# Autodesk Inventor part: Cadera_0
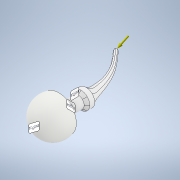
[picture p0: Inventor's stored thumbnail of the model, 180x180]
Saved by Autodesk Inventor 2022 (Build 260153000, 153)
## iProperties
Created: 2022-05
Part Number: Cadera_0
Material: Generic
Document SubType Name: Modeling
Designer: Administrator
Density: 1 g/cm^3
Appearance: Default
Title: Cadera_0 v3
Author: Administrator
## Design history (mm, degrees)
feature "Pieza_1"
feature "Pieza_2"
body "Solid1"
body "Solid2"
other parameters: "sa_0" = 344737.86466, "sa_1" = 1034213.59398, "sa_2" = 2224110.80763, "sa_3" = 2224110.80763, "sa_4" = 2224110.80763
